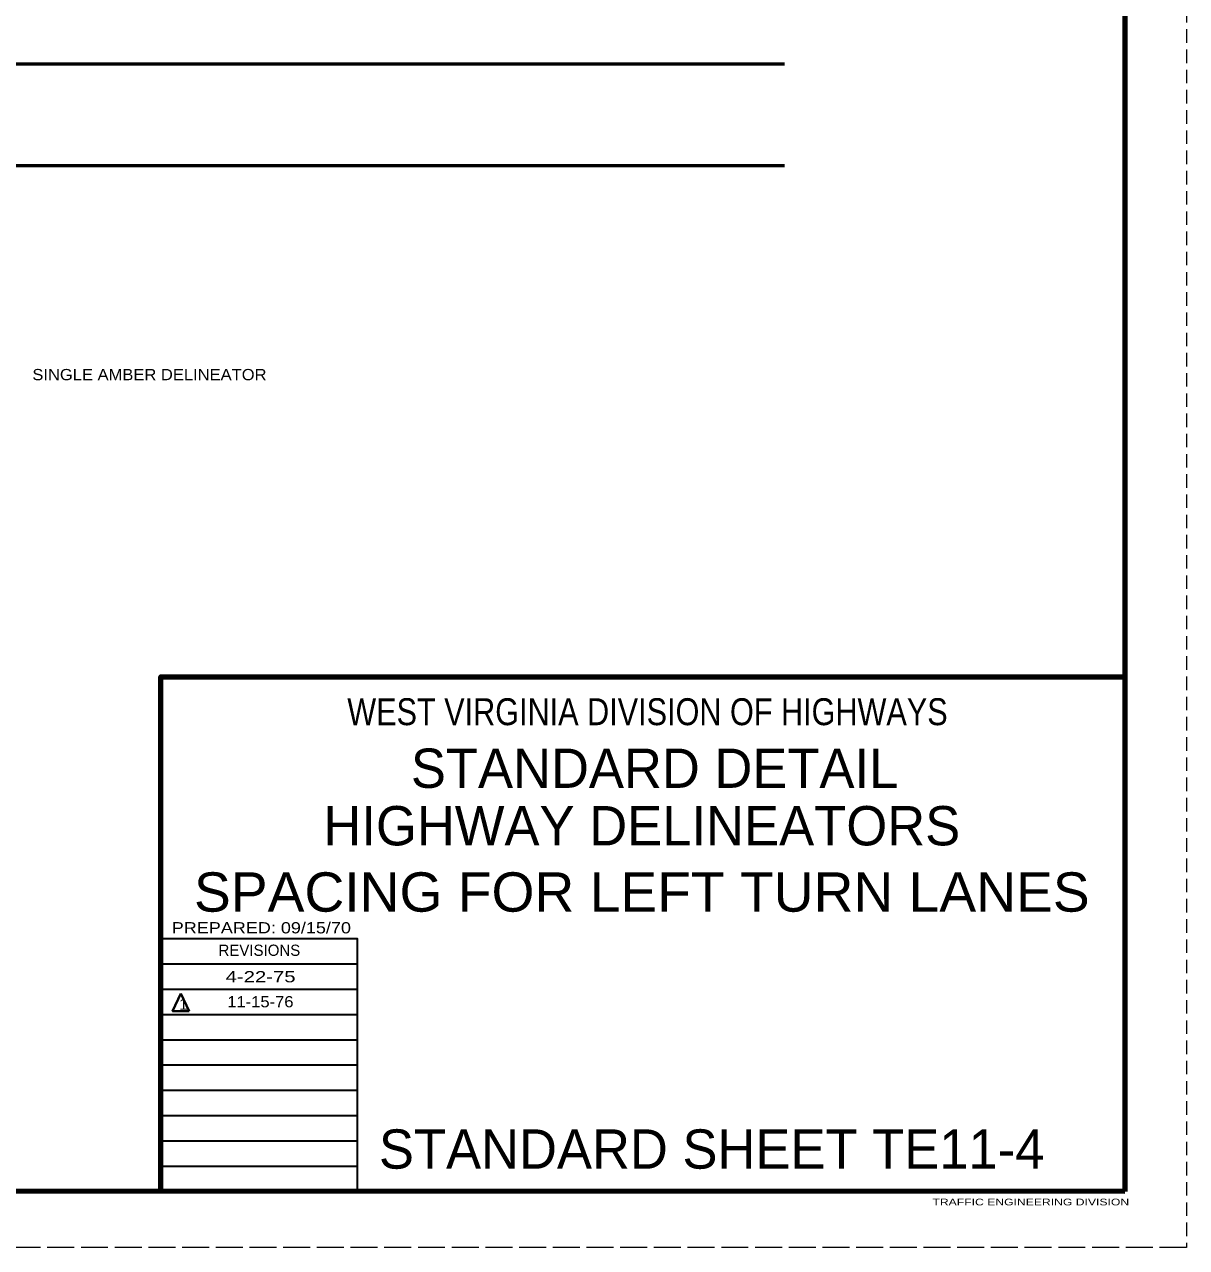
# Model space of a CAD drawing. Extents: x -280 to 400, y 15 to 456.
# Drawn here: x 193.3 to 400.2, y 15.5 to 233.2 of the extents above; entities that cross this region are included whole.
import ezdxf
from ezdxf.enums import TextEntityAlignment as Align

# ---------------------------------------------------------------- set-up
doc = ezdxf.new("R2010")
doc.units = 0
doc.header["$LTSCALE"] = 0.8
doc.linetypes.add('LONG_DASHED', pattern=[7.5, 6, -1.5])
doc.linetypes.add('MEDIUM_DASHED', pattern=[4.5, 3, -1.5])
doc.layers.add('1', color=7, linetype='Continuous', lineweight=53)
doc.layers.add('61', color=7, linetype='Continuous', lineweight=35)

msp = doc.modelspace()

# ---------------------------------------------------------------- linework, layer by layer
at = {"layer": '1', "linetype": 'MEDIUM_DASHED', "lineweight": 13}
msp.add_line((400.1618, 455.5237), (400.1418, 15.5037), dxfattribs=at)
at = {"layer": '1'}
for p, q in [((328.5872, 226.1099), (125.4173, 226.1099)), ((149.0672, 208.1099), (328.5872, 208.1099))]:
    msp.add_line(p, q, dxfattribs=at)
at = {"layer": '1', "lineweight": 35}
for p, q in [((252.5418, 65.9237), (217.5618, 65.9237)), ((252.5418, 61.4237), (217.5618, 61.4237)), ((252.5418, 56.9237), (217.5618, 56.9237)), ((252.5418, 52.4037), (217.5618, 52.4037)), ((252.5418, 47.9237), (217.5618, 47.9237)), ((252.5418, 43.4437), (217.5618, 43.4437)), ((252.5418, 38.9437), (217.5618, 38.9437)), ((252.5418, 34.4437), (217.5618, 34.4437)), ((252.5418, 29.9237), (217.5618, 29.9237))]:
    msp.add_line(p, q, dxfattribs=at)
at = {"layer": '1', "lineweight": 40}
msp.add_line((221.1072, 60.727), (222.5773, 57.5742), dxfattribs=at)
at = {"layer": '1', "lineweight": 158}
msp.add_lwpolyline([(217.5418, 25.4837), (217.5418, 117.0637), (389.2018, 117.0637)], dxfattribs=at)
at = {"layer": '1', "lineweight": 35}
msp.add_lwpolyline([(252.5418, 25.4437), (252.5418, 70.4037), (217.5618, 70.4037)], dxfattribs=at)
at = {"layer": '1', "lineweight": 40}
msp.add_lwpolyline([(221.1072, 60.727), (219.6371, 57.5742), (222.5773, 57.5742)], dxfattribs=at)
at = {"layer": '61', "lineweight": 158}
for p, q in [((389.1818, 445.5237), (389.2018, 25.4837)), ((389.2018, 25.4837), (-249.8582, 25.5037))]:
    msp.add_line(p, q, dxfattribs=at)
at = {"layer": '61', "linetype": 'LONG_DASHED', "lineweight": 13}
msp.add_line((400.1418, 15.5037), (-279.9182, 15.4837), dxfattribs=at)

# ---------------------------------------------------------------- texts
at = {"layer": '1'}
for s, height, width, p in [('SINGLE AMBER DELINEATOR', 2, 1.1, (194.681, 169.8663)), ('PREPARED: 09/15/70', 1.998, 1.2, (219.5018, 71.4037)), ('4-22-75', 2, 1.35, (229.0902, 62.6885)), ('11-15-76', 2, 1.1, (229.3911, 58.2418)), ('TRAFFIC ENGINEERING DIVISION', 1.2, 1.35, (354.9218, 22.9837))]:
    msp.add_text(s, height=height, dxfattribs=dict(at, width=width)).set_placement(p)
for s, height, width, p in [('WEST VIRGINIA DIVISION OF HIGHWAYS', 4.795, 0.85, (304.1902, 108.4637)), ('SPACING FOR LEFT TURN LANES', 7, 1.05, (303.182, 75.2661))]:
    msp.add_text(s, height=height, dxfattribs=dict(at, width=width)).set_placement(p, align=Align.CENTER)
for s, height, p in [('STANDARD DETAIL', 6.993, (305.4588, 97.3037)), ('HIGHWAY DELINEATORS', 7, (303.182, 87.0661))]:
    msp.add_text(s, height=height, dxfattribs=at).set_placement(p, align=Align.CENTER)
for s, height, p in [('REVISIONS', 1.998, (227.8218, 67.4037)), ('1', 2, (220.8311, 57.8068)), ('STANDARD SHEET TE11-4', 6.993, (256.3818, 29.5237))]:
    msp.add_text(s, height=height, dxfattribs=at).set_placement(p)

doc.saveas('drawing.dxf')
